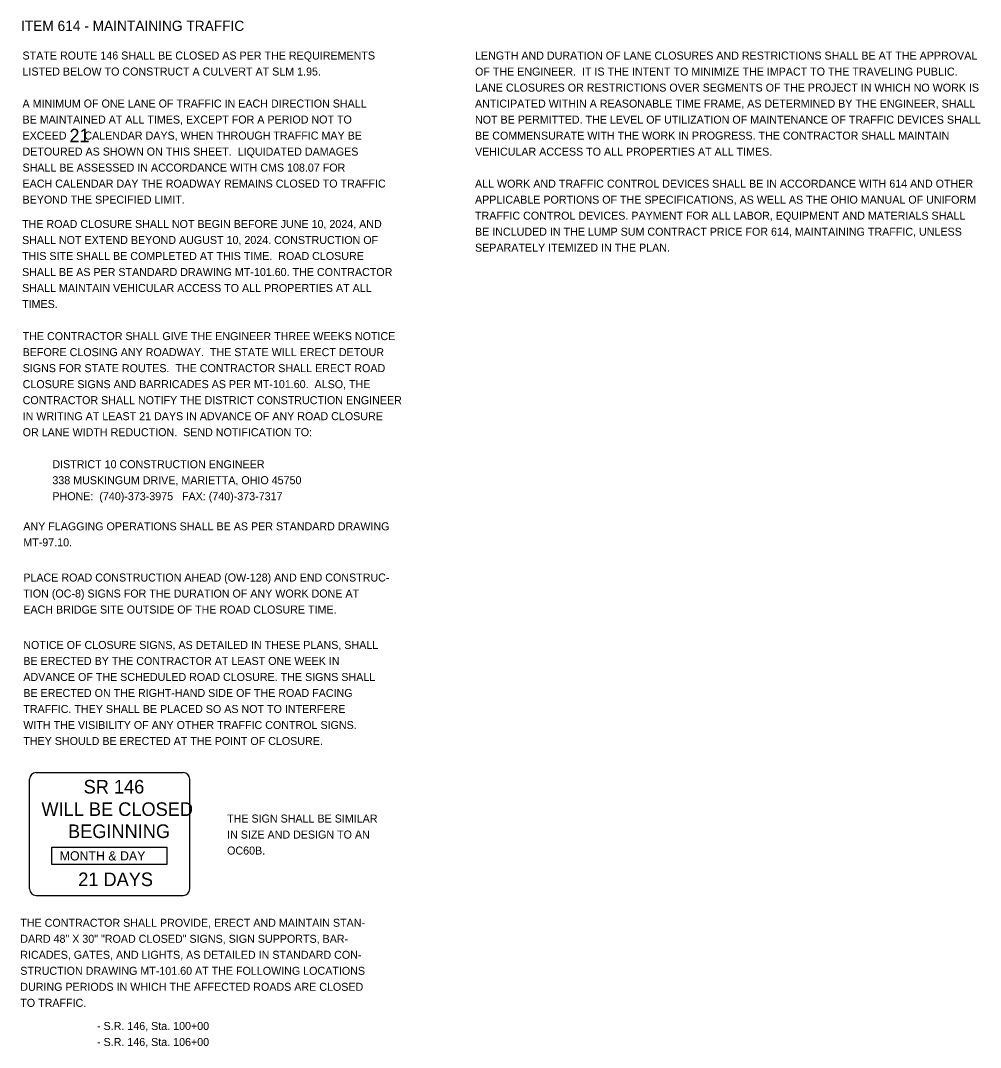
# Model space of a CAD drawing. Extents: x -452339 to 6403467, y -1 to 1814750.
# Drawn here: x -207081 to -108243, y 1435764 to 1541434 of the extents above; entities that cross this region are included whole.
import ezdxf

# ---------------------------------------------------------------- set-up
doc = ezdxf.new("R2010")
doc.units = 0
doc.layers.add('Default', color=7, linetype='Continuous')

msp = doc.modelspace()

# ---------------------------------------------------------------- linework, layer by layer
at = {"layer": 'Default'}
for p, q in [((-205468, 1464048), (-190341, 1464048)), ((-206155, 1452087), (-206155, 1463362)), ((-189655, 1452087), (-189655, 1463362)), ((-205468, 1451400), (-190341, 1451400))]:
    msp.add_line(p, q, dxfattribs=at)
msp.add_lwpolyline([(-203870, 1456361), (-192004, 1456361), (-192004, 1454595), (-203870, 1454595)], close=True, dxfattribs=at)
for centre, start, end in [((-205469, 1463362), 90, 180), ((-190342, 1463362), 0, 90), ((-205469, 1452087), 180, 270), ((-190342, 1452087), 270, 360)]:
    msp.add_arc(centre, 686, start, end, dxfattribs=at)

# ---------------------------------------------------------------- texts
for s, height, p in [('ITEM 614 - MAINTAINING TRAFFIC', 1056, (-207033, 1540362)), ('STATE ROUTE 146 SHALL BE CLOSED AS PER THE REQUIREMENTS', 823.68, (-206875, 1537423)), ('LENGTH AND DURATION OF LANE CLOSURES AND RESTRICTIONS SHALL BE AT THE APPROVAL', 823.68, (-160287, 1537416)), ('LISTED BELOW TO CONSTRUCT A CULVERT AT SLM 1.95. ', 823.68, (-206875, 1535775)), ('OF THE ENGINEER.  IT IS THE INTENT TO MINIMIZE THE IMPACT TO THE TRAVELING PUBLIC.', 823.68, (-160287, 1535769)), ('LANE CLOSURES OR RESTRICTIONS OVER SEGMENTS OF THE PROJECT IN WHICH NO WORK IS', 823.68, (-160287, 1534121)), ('A MINIMUM OF ONE LANE OF TRAFFIC IN EACH DIRECTION SHALL', 823.68, (-206875, 1532481)), ('ANTICIPATED WITHIN A REASONABLE TIME FRAME, AS DETERMINED BY THE ENGINEER, SHALL', 823.68, (-160287, 1532474)), ('BE MAINTAINED AT ALL TIMES, EXCEPT FOR A PERIOD NOT TO', 823.68, (-206875, 1530833)), ('NOT BE PERMITTED. THE LEVEL OF UTILIZATION OF MAINTENANCE OF TRAFFIC DEVICES SHALL', 823.68, (-160287, 1530826)), ('21', 1374.6, (-202034, 1528916)), ('EXCEED      CALENDAR DAYS, WHEN THROUGH TRAFFIC MAY BE', 823.68, (-206875, 1529186)), ('BE COMMENSURATE WITH THE WORK IN PROGRESS. THE CONTRACTOR SHALL MAINTAIN', 823.68, (-160287, 1529179)), ('DETOURED AS SHOWN ON THIS SHEET.  LIQUIDATED DAMAGES', 823.68, (-206875, 1527538)), ('VEHICULAR ACCESS TO ALL PROPERTIES AT ALL TIMES.', 823.68, (-160287, 1527532)), ('SHALL BE ASSESSED IN ACCORDANCE WITH CMS 108.07 FOR', 823.68, (-206875, 1525891)), ('EACH CALENDAR DAY THE ROADWAY REMAINS CLOSED TO TRAFFIC', 823.68, (-206875, 1524244)), ('ALL WORK AND TRAFFIC CONTROL DEVICES SHALL BE IN ACCORDANCE WITH 614 AND OTHER', 823.68, (-160287, 1524237)), ('BEYOND THE SPECIFIED LIMIT.', 823.68, (-206875, 1522596)), ('APPLICABLE PORTIONS OF THE SPECIFICATIONS, AS WELL AS THE OHIO MANUAL OF UNIFORM', 823.68, (-160287, 1522590)), ('TRAFFIC CONTROL DEVICES. PAYMENT FOR ALL LABOR, EQUIPMENT AND MATERIALS SHALL', 823.68, (-160287, 1520942)), ('THE ROAD CLOSURE SHALL NOT BEGIN BEFORE JUNE 10, 2024, AND', 823.68, (-206921, 1520088)), ('BE INCLUDED IN THE LUMP SUM CONTRACT PRICE FOR 614, MAINTAINING TRAFFIC, UNLESS', 823.68, (-160287, 1519295)), ('SHALL NOT EXTEND BEYOND AUGUST 10, 2024. CONSTRUCTION OF', 823.68, (-206921, 1518440)), ('SEPARATELY ITEMIZED IN THE PLAN.', 823.68, (-160287, 1517648)), ('THIS SITE SHALL BE COMPLETED AT THIS TIME.  ROAD CLOSURE', 823.68, (-206921, 1516793)), ('SHALL BE AS PER STANDARD DRAWING MT-101.60. THE CONTRACTOR', 823.68, (-206921, 1515145)), ('SHALL MAINTAIN VEHICULAR ACCESS TO ALL PROPERTIES AT ALL', 823.68, (-206921, 1513498)), ('TIMES.', 823.7, (-206921, 1511851)), ('THE CONTRACTOR SHALL GIVE THE ENGINEER THREE WEEKS NOTICE', 823.68, (-206861, 1508548)), ('BEFORE CLOSING ANY ROADWAY.  THE STATE WILL ERECT DETOUR', 823.68, (-206861, 1506900)), ('SIGNS FOR STATE ROUTES.  THE CONTRACTOR SHALL ERECT ROAD', 823.68, (-206861, 1505253)), ('CLOSURE SIGNS AND BARRICADES AS PER MT-101.60.  ALSO, THE', 823.68, (-206861, 1503606)), ('CONTRACTOR SHALL NOTIFY THE DISTRICT CONSTRUCTION ENGINEER', 823.68, (-206861, 1501958)), ('IN WRITING AT LEAST 21 DAYS IN ADVANCE OF ANY ROAD CLOSURE', 823.68, (-206861, 1500311)), ('OR LANE WIDTH REDUCTION.  SEND NOTIFICATION TO:', 823.68, (-206861, 1498664)), ('          DISTRICT 10 CONSTRUCTION ENGINEER', 823.68, (-206861, 1495369)), ('          338 MUSKINGUM DRIVE, MARIETTA, OHIO 45750', 823.68, (-206861, 1493722)), ('          PHONE:  (740)-373-3975   FAX: (740)-373-7317', 823.68, (-206861, 1492074)), ('ANY FLAGGING OPERATIONS SHALL BE AS PER STANDARD DRAWING', 823.68, (-206794, 1488974)), ('MT-97.10.', 823.7, (-206794, 1487327)), ('PLACE ROAD CONSTRUCTION AHEAD (OW-128) AND END CONSTRUC-', 823.68, (-206794, 1483710)), ('TION (OC-8) SIGNS FOR THE DURATION OF ANY WORK DONE AT', 823.68, (-206794, 1482062)), ('EACH BRIDGE SITE OUTSIDE OF THE ROAD CLOSURE TIME.', 823.68, (-206794, 1480415)), ('NOTICE OF CLOSURE SIGNS, AS DETAILED IN THESE PLANS, SHALL', 823.68, (-206794, 1476771)), ('BE ERECTED BY THE CONTRACTOR AT LEAST ONE WEEK IN', 823.68, (-206794, 1475124)), ('ADVANCE OF THE SCHEDULED ROAD CLOSURE. THE SIGNS SHALL', 823.68, (-206794, 1473476)), ('BE ERECTED ON THE RIGHT-HAND SIDE OF THE ROAD FACING', 823.68, (-206794, 1471829)), ('TRAFFIC. THEY SHALL BE PLACED SO AS NOT TO INTERFERE', 823.68, (-206794, 1470182)), ('WITH THE VISIBILITY OF ANY OTHER TRAFFIC CONTROL SIGNS.', 823.68, (-206794, 1468534)), ('THEY SHOULD BE ERECTED AT THE POINT OF CLOSURE.', 823.68, (-206794, 1466887)), ('SR 146', 1400, (-200583, 1461896)), ('WILL BE CLOSED', 1400, (-204929, 1459586)), ('THE SIGN SHALL BE SIMILAR', 823.68, (-185811, 1458907)), ('BEGINNING', 1400, (-202189, 1457314)), ('IN SIZE AND DESIGN TO AN', 823.68, (-185811, 1457260)), ('OC60B.', 823.7, (-185811, 1455612)), ('MONTH & DAY', 950.4, (-203049, 1455003)), ('21 DAYS', 1400, (-201140, 1452366)), ('THE CONTRACTOR SHALL PROVIDE, ERECT AND MAINTAIN STAN-', 823.68, (-207105, 1448181)), ('DARD 48" X 30" "ROAD CLOSED" SIGNS, SIGN SUPPORTS, BAR-', 823.68, (-207105, 1446533)), ('RICADES, GATES, AND LIGHTS, AS DETAILED IN STANDARD CON-', 823.68, (-207105, 1444886)), ('STRUCTION DRAWING MT-101.60 AT THE FOLLOWING LOCATIONS', 823.68, (-207105, 1443239)), ('DURING PERIODS IN WHICH THE AFFECTED ROADS ARE CLOSED', 823.68, (-207105, 1441591)), ('TO TRAFFIC.', 823.68, (-207105, 1439944)), ('  - S.R. 146, Sta. 100+00', 823.68, (-199815, 1437564)), ('  - S.R. 146, Sta. 106+00', 823.68, (-199815, 1435917))]:
    msp.add_text(s, height=height, dxfattribs=at).set_placement(p)

doc.saveas('drawing.dxf')
